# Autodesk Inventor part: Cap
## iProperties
Shininess: 77.0
Length Units: 11269
Angle Units: 11279
Time Units: 11290
Mass Units: 11283
Length Display Precision: 3
Angle Display Precision: 2
Created: 2002-02
Part Number: Cap
Document SubType Name: Modeling
Designer: ***
Density: 1 g/cm^3
Density: 0.0
Volumn: 0.0
Area: 0.0
PropertySet Name: Model Information
Control State: 0
Master: False
Checked Out: False
Author: ***
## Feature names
1. Extrusion1
2. Extrusion2
3. Mirror1
4. Hole1
5. Rectangular Pattern1
6. Hole2
7. Rectangular Pattern2
